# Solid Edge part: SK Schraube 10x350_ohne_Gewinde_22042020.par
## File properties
Author: fknapp
Template: Normal.par
Last saved by: fknapp
Revision: 29
Application: Solid Edge
Username: fknapp
Material: Aluminium
Genauigkeit: 0,99
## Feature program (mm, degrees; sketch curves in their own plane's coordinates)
sketch for "unnamed RevolvedProtrusion 1" plane through (0, 0, 0) normal (0, 0, 1) x-axis (1, 0, 0)
  line (0, 54) -> (9, 54)
  line (9, 54) -> (9, 53)
  line (9, 53) -> (5, 49)
  line (5, 49) -> (5, 46.3)
  line (5, 46.3) -> (4.7548, 46.3)
  arc centre (4.7548, 44.6952) radius 1.6048 from (4.7548, 46.3) to (3.15, 44.6952) ccw
  line (3.15, 44.6952) -> (3.15, 42)
  line (3.15, 42) -> (5, 42)
  line (5, -283) -> (5, 42)
  line (0.5, -296) -> (5, -283)
  line (0, -296) -> (0.5, -296)
revolve "unnamed RevolvedProtrusion 1" add full turn 360 deg about sketch line (0, 54) -> (0, -296)
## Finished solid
Body 1: solid body, 11 faces, 10 edges, 0 vertices.
  Faces by surface: cylinder 4, plane 4, cone 2, torus 1
  Edges by curve: circle 10
Bounding box of the edges (mm; curved faces can reach further): 18.000 x 350.000 x 18.000, from (-9, -296, -9) to (9, 54, 9).
Cylindrical faces by radius (mm): R3.15 x1, R5 x2, R9 x1
Conical faces (half-angle, radius in mm at the cone's reference point): 19.0935 deg R5 x1, 45 deg R9 x1
Toroidal faces (ring radius, tube radius in mm): R4.7548 r1.6048 x1
Planar faces by outward normal: +y 2, -y 2
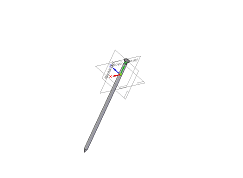
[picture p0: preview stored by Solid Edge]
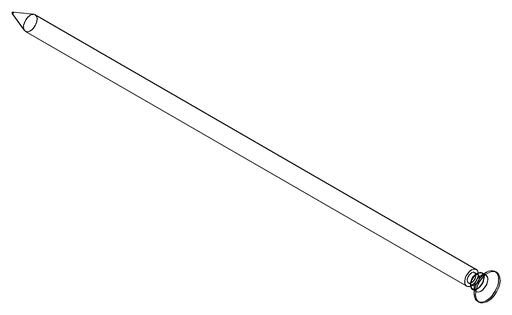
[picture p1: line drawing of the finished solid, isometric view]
